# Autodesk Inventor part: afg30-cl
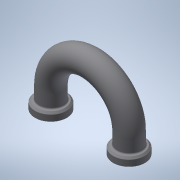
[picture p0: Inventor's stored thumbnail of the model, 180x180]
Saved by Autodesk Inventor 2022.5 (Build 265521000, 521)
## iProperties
Created: 2016-12
Part Number: afg30-cl
Material: 一般
Document SubType Name: Modeling
Designer: imaocorp
Density: 1 g/cm^3
Appearance: 既定
Author: imaocorp
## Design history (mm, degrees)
node "afg30-cl.x_t1"
node "afg30-cl"
node "Base1"
